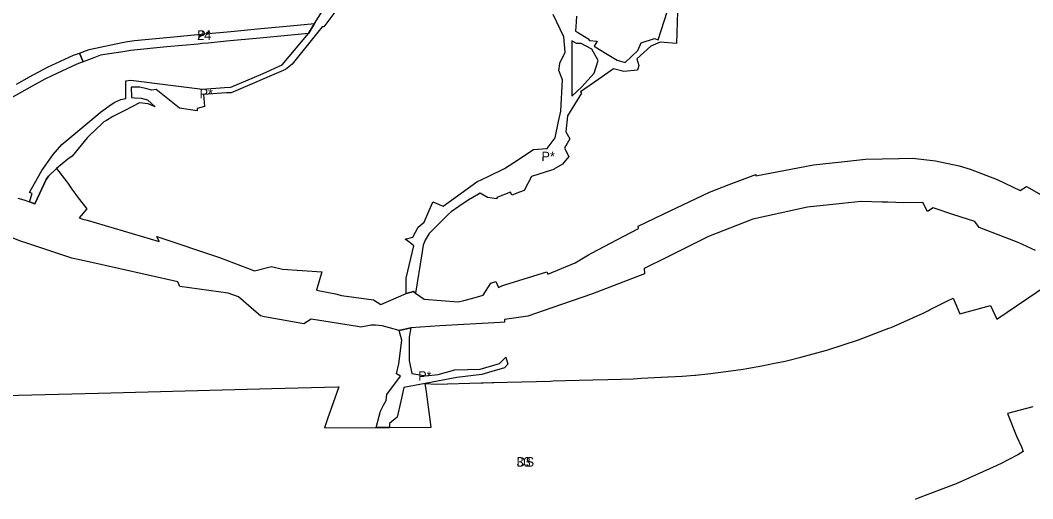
# Model space of a CAD drawing. Extents: x -501732 to -497665, y -1142022 to -1138283.
# Drawn here: x -498822 to -498074, y -1140690 to -1140337 of the extents above; entities that cross this region are included whole.
import ezdxf

# ---------------------------------------------------------------- set-up
doc = ezdxf.new("R2010")
doc.units = 0
for name, color, linetype in [('43', 7, 'Continuous'), ('44', 7, 'Continuous'), ('5', 7, 'Continuous'), ('61', 7, 'Continuous'), ('7', 7, 'Continuous')]:
    doc.layers.add(name, color=color, linetype=linetype)

msp = doc.modelspace()

# ---------------------------------------------------------------- linework, layer by layer
at = {"layer": '43'}
for points in [[(-498587.81, -1140329.06), (-498597.43, -1140341.87), (-498598.8, -1140341.98), (-498601.88, -1140345.827), (-498620.83, -1140369.5), (-498625.74, -1140373.36), (-498665.8, -1140390.54), (-498669.367, -1140390.774), (-498686.38, -1140391.89), (-498685.66, -1140400.64), (-498690.99, -1140402.25), (-498690.95, -1140403.93), (-498703.99, -1140401.95), (-498721.27, -1140388.18), (-498724.52, -1140388.76), (-498728.2, -1140387.65), (-498733.35, -1140386.55), (-498735.97, -1140386.48), (-498737.7, -1140386.43), (-498739.75, -1140386.38), (-498739.51, -1140394.23), (-498737.19, -1140394.36), (-498732.26, -1140394.64), (-498727.49, -1140395.85), (-498722.04, -1140400.93), (-498727.09, -1140398.67), (-498733.56, -1140397.95), (-498744.45, -1140403.69), (-498753.11, -1140408.26), (-498757.95, -1140411.07), (-498759.89, -1140412.2), (-498761.398, -1140413.616), (-498770.22, -1140421.9), (-498772.24, -1140423.88), (-498783.3, -1140437.31), (-498786.33, -1140439.72), (-498794.66, -1140446.57), (-498800.7, -1140452.21), (-498802.45, -1140454.72), (-498810.69, -1140472.63), (-498814.8, -1140471.18), (-498812.74, -1140465.05), (-498814.61, -1140464.19), (-498813.3, -1140461.48), (-498805.54, -1140447.97), (-498798.911, -1140438.777), (-498797.14, -1140436.32), (-498790.77, -1140428.9), (-498764.36, -1140406.72), (-498762.37, -1140405.04), (-498754.41, -1140399.29), (-498751.71, -1140397.67), (-498747.2, -1140395.62), (-498743.556, -1140394.77), (-498743.53, -1140387.04), (-498743.67, -1140383.35), (-498743.706, -1140381.726), (-498739.8, -1140381.33), (-498710.55, -1140385.04), (-498687.02, -1140387.86), (-498670.81, -1140386.81), (-498666.17, -1140386.51), (-498642.15, -1140376.28), (-498628.17, -1140370.07), (-498608.89, -1140346.84), (-498606.59, -1140343.1), (-498604.38, -1140339.37), (-498585.04, -1140308.39)], [(-498336.48, -1140330.57), (-498337.19, -1140354.3), (-498349.26, -1140353.22), (-498356.2, -1140356.09), (-498366.38, -1140365.47), (-498365.05, -1140370.57), (-498366.07, -1140373.97), (-498375.98, -1140374.82), (-498383.77, -1140372.94), (-498394.58, -1140380.5), (-498408.12, -1140389.97), (-498407.39, -1140390.94), (-498417.76, -1140407.66), (-498418.97, -1140419.34), (-498415.94, -1140424.67), (-498419.83, -1140431.49), (-498416.7, -1140437.75), (-498421.35, -1140443.39), (-498427.73, -1140447.08), (-498427.61, -1140447.29), (-498429.55, -1140447.88), (-498444.21, -1140452.41), (-498449.63, -1140462.74), (-498452.98, -1140464), (-498458.85, -1140466.21), (-498459.06, -1140465.62), (-498459.66, -1140463.92), (-498469.92, -1140467.89), (-498469.79, -1140469.06), (-498476.72, -1140467.87), (-498482.04, -1140464.87), (-498488.75, -1140468.62), (-498489.42, -1140468.99), (-498497.76, -1140474.62), (-498503.53, -1140478.64), (-498505.6, -1140480.51), (-498519.81, -1140494.63), (-498522.78, -1140499.54), (-498524.16, -1140503.18), (-498525.13, -1140509.48), (-498529.72, -1140538.53), (-498531.23, -1140537.43), (-498536.7, -1140538.87), (-498536.78, -1140527.54), (-498530.96, -1140503.56), (-498532.27, -1140502.58), (-498534, -1140501.29), (-498537.44, -1140498.71), (-498531.9, -1140497.34), (-498527.88, -1140489.95), (-498523.44, -1140486.2), (-498521.29, -1140481.1), (-498517.37, -1140471.8), (-498517.14, -1140471.25), (-498509.39, -1140474.46), (-498503.28, -1140470.04), (-498484.44, -1140456.39), (-498476.27, -1140452.44), (-498464.24, -1140446.62), (-498457.324, -1140442.101), (-498442.71, -1140432.55), (-498432.73, -1140431.71), (-498426.65, -1140423.95), (-498424.26, -1140411.9), (-498422.65, -1140404.29), (-498421.42, -1140381), (-498424.07, -1140374.16), (-498423.9, -1140372.85), (-498423.35, -1140368.66), (-498419.46, -1140360.65), (-498420.41, -1140349.26), (-498428.12, -1140332.76)], [(-498410.95, -1140334.03), (-498411.23, -1140338.15), (-498411.64, -1140345.19), (-498409.63, -1140346.38), (-498402.59, -1140350.64), (-498402.44, -1140350.81), (-498401.44, -1140351.96), (-498395.69, -1140352.4), (-498398.08, -1140356.26), (-498394, -1140358.78), (-498388.346, -1140362.103), (-498380.9, -1140366.48), (-498375.18, -1140368.36), (-498365.85, -1140359.51), (-498363.35, -1140353.74), (-498353.52, -1140350.55), (-498350.67, -1140351.45), (-498343.94, -1140330.1)], [(-498824.33, -1140384.17), (-498814.604, -1140378.848), (-498801.52, -1140371.69), (-498782.25, -1140362.86), (-498777.9, -1140361.33), (-498774.98, -1140367.75), (-498779.77, -1140369.59), (-498798.09, -1140378.22), (-498803.38, -1140380.68), (-498812.777, -1140385.826), (-498820.71, -1140390.17), (-498838.52, -1140399.91)]]:
    msp.add_lwpolyline(points, dxfattribs=at)
for points in [[(-498397.99, -1140376.21), (-498395.01, -1140366.78), (-498399.65, -1140358.41), (-498407.49, -1140354.32), (-498411.1, -1140354.18), (-498414.49, -1140352.22), (-498414.41, -1140393.14), (-498407.33, -1140386.52)], [(-498532.65, -1140598.05), (-498522.19, -1140599.71), (-498513.12, -1140598.78), (-498500.8, -1140595.31), (-498482.14, -1140594.81), (-498467.72, -1140590.56), (-498463.18, -1140585.79), (-498461.584, -1140591.01), (-498464.1, -1140593.8), (-498473.43, -1140596.49), (-498480.9, -1140598.67), (-498499.44, -1140600.8), (-498522.66, -1140605.32), (-498538.35, -1140608.28), (-498540.69, -1140618.47), (-498543.28, -1140630.12), (-498549.01, -1140634.74), (-498549.008, -1140637.715), (-498558.761, -1140637.77), (-498555.71, -1140625.83), (-498553.43, -1140621.2), (-498551.35, -1140617.79), (-498551.07, -1140613.42), (-498540.82, -1140599.94), (-498543.73, -1140598.24), (-498542.14, -1140590.72), (-498539.91, -1140573.24), (-498541.95, -1140566.19), (-498533.275, -1140564.275), (-498534.38, -1140571.05), (-498534.41, -1140583.39), (-498534.44, -1140588.39)]]:
    msp.add_lwpolyline(points, close=True, dxfattribs=at)
at = {"layer": '44'}
msp.add_lwpolyline([(-498608.89, -1140346.84), (-498644.63, -1140350.25), (-498669.42, -1140352.61), (-498682.81, -1140353.868), (-498687.19, -1140354.28), (-498690.21, -1140354.6), (-498713.32, -1140356.8), (-498740.24, -1140359.37), (-498744.18, -1140360.16), (-498762.2, -1140362.83), (-498767.22, -1140364.9), (-498774.98, -1140367.75), (-498777.9, -1140361.33), (-498770.58, -1140358.75), (-498746.33, -1140353.43), (-498742.44, -1140352.65), (-498737.12, -1140352.09), (-498710.8, -1140349.53), (-498687.95, -1140347.35), (-498685.278, -1140347.095), (-498666.05, -1140345.26), (-498643.95, -1140343.16), (-498622.2, -1140341.08), (-498604.38, -1140339.37), (-498606.59, -1140343.1)], close=True, dxfattribs=at)
at = {"layer": '5'}
for points in [[(-498911.97, -1140616.22), (-498763.779, -1140612.414), (-498635.836, -1140608.996), (-498587.232, -1140607.698), (-498586.309, -1140607.658), (-498594.68, -1140631.38), (-498596.956, -1140637.987), (-498558.761, -1140637.77), (-498549.008, -1140637.715), (-498518.24, -1140637.54), (-498521.824, -1140611.416), (-498522.66, -1140605.32), (-498514.662, -1140605.76), (-498481.482, -1140604.874), (-498479.827, -1140604.83), (-498473.333, -1140604.656), (-498471.913, -1140604.618), (-498462.065, -1140604.355), (-498440.64, -1140603.783), (-498430.138, -1140603.502), (-498428.221, -1140603.451), (-498419.006, -1140603.196), (-498398.992, -1140602.641), (-498387.928, -1140602.335), (-498377.939, -1140602.058), (-498369.099, -1140601.813), (-498363.353, -1140601.491), (-498343.694, -1140600.388), (-498343.303, -1140600.366), (-498333.112, -1140599.794), (-498323.736, -1140599.268), (-498323.104, -1140599.19), (-498314.182, -1140598.086), (-498304.366, -1140596.872), (-498287.957, -1140594.843), (-498285.35, -1140594.337), (-498274.137, -1140592.159), (-498264.802, -1140590.346), (-498257.129, -1140588.856), (-498255.131, -1140588.333), (-498245.571, -1140585.832), (-498227.312, -1140581.055), (-498225.57, -1140580.489), (-498202.84, -1140573.11), (-498196.526, -1140570.684), (-498180.452, -1140564.508), (-498178.766, -1140563.86), (-498155.285, -1140553.385), (-498151.261, -1140551.331), (-498150.408, -1140550.895), (-498137.212, -1140544.157), (-498133.079, -1140542.247), (-498132.18, -1140543.96), (-498128.1, -1140553.78), (-498105.46, -1140547.59), (-498100.702, -1140557.857), (-498049.646, -1140523.081)], [(-498074.25, -1140622.66), (-498092.81, -1140627.56), (-498086.34, -1140644.21), (-498082.67, -1140652.13), (-498081.436, -1140655.582), (-498085.369, -1140658.038), (-498098.651, -1140664.82), (-498099.854, -1140665.434), (-498101.363, -1140666.204), (-498130.852, -1140679.36), (-498140.654, -1140683.126), (-498158.761, -1140690.084), (-498161.095, -1140690.981)]]:
    msp.add_lwpolyline(points, dxfattribs=at)
at = {"layer": '7'}
for points in [[(-498823.28, -1140468.41), (-498818.81, -1140469.76), (-498814.8, -1140471.18), (-498810.69, -1140472.63), (-498802.45, -1140454.72), (-498800.7, -1140452.21), (-498794.66, -1140446.57), (-498792.98, -1140448.82), (-498786.49, -1140457.49), (-498785.41, -1140458.93), (-498783.46, -1140461.83), (-498778.67, -1140468.13), (-498772.46, -1140476.29), (-498778.07, -1140483.03), (-498775.4, -1140483.86), (-498772.22, -1140484.8), (-498719.07, -1140500.44), (-498720.83, -1140496.71), (-498674.39, -1140512.29), (-498648.73, -1140522.18), (-498635.98, -1140518.93), (-498627.99, -1140520.95), (-498598.96, -1140522.87), (-498602.81, -1140536.42), (-498588.8, -1140539.12), (-498584.45, -1140540.28), (-498560.9, -1140543.44), (-498558.02, -1140545.17), (-498555.32, -1140546.97), (-498536.7, -1140538.87), (-498531.23, -1140537.43), (-498529.72, -1140538.53), (-498523.42, -1140543.13), (-498498.25, -1140544.96), (-498494.14, -1140543.93), (-498487.43, -1140542.26), (-498479.83, -1140540.06), (-498474.26, -1140531.16), (-498470.5, -1140530.11), (-498468.47, -1140534.46), (-498466.08, -1140533.14), (-498463.8, -1140532.43), (-498432.86, -1140522.77), (-498432.24, -1140524.64), (-498411.97, -1140516.09), (-498402.08, -1140510.39), (-498399.36, -1140508.79), (-498385.8, -1140501.68), (-498365.23, -1140490.89), (-498365.57, -1140489.11), (-498347.06, -1140480.37), (-498312.78, -1140463.9), (-498298.318, -1140458.398), (-498278.66, -1140450.92), (-498278.63, -1140451.9), (-498236, -1140443.78), (-498215.5, -1140441.58), (-498197.67, -1140439.66), (-498173.045, -1140439.206), (-498162.95, -1140439.02), (-498145.98, -1140440.86), (-498128.48, -1140444.52), (-498120.5, -1140446.95), (-498100.63, -1140454.71), (-498083.46, -1140462.79), (-498078.87, -1140459.94), (-498066.42, -1140467)], [(-498072.23, -1140507.08), (-498084.94, -1140501.15), (-498113.82, -1140490.04), (-498116.99, -1140485.75), (-498133.19, -1140480.39), (-498147.91, -1140475.52), (-498151.9, -1140478.35), (-498155.29, -1140471.77), (-498169.43, -1140471.87), (-498181.21, -1140471.48), (-498185.33, -1140471.34), (-498200.94, -1140470.83), (-498215.03, -1140472.28), (-498240.65, -1140475.14), (-498280.79, -1140483.97), (-498313.48, -1140496.67), (-498344.08, -1140511.99), (-498360.97, -1140520.45), (-498360.76, -1140524.45), (-498399.15, -1140539.13), (-498429.13, -1140549.46), (-498447.03, -1140555.63), (-498464.11, -1140558.05), (-498464.12, -1140560.13), (-498467.4, -1140560.31), (-498511.96, -1140562.69), (-498533.275, -1140564.275), (-498541.95, -1140566.19), (-498548.93, -1140564.16), (-498554.35, -1140562.68), (-498559.27, -1140562.23), (-498562.5, -1140562.23), (-498570.08, -1140563.64), (-498572.57, -1140563.26), (-498606.84, -1140557.72), (-498612.14, -1140561.31), (-498641.22, -1140555.98), (-498644.25, -1140555.43), (-498647.38, -1140552.52), (-498660.45, -1140541.37), (-498668.06, -1140538.59), (-498703.71, -1140533.76), (-498705.24, -1140530.18), (-498770.79, -1140515.52), (-498783.43, -1140512.69), (-498817.31, -1140501.5), (-498820.56, -1140500.53), (-498829.89, -1140496.72)]]:
    msp.add_lwpolyline(points, dxfattribs=at)

# ---------------------------------------------------------------- texts
at = {"layer": '43'}
for rotation, p in [(359.497419, (-498689.197, -1140394.656)), (359.497417, (-498436.892, -1140441.113))]:
    msp.add_text('P*', height=7, rotation=rotation, dxfattribs=at).set_placement(p)
msp.add_text('P*', height=7, dxfattribs=at).set_placement((-498527.876, -1140603.236))
at = {"layer": '44'}
msp.add_text('P*', height=7, dxfattribs=at).set_placement((-498690.962, -1140351.544))
at = {"layer": '5'}
msp.add_text('DS', height=7, dxfattribs=at).set_placement((-498455.24, -1140666.691))
at = {"layer": '61'}
for s, p in [('24', (-498690.962, -1140351.544)), ('33', (-498455.256, -1140666.691))]:
    msp.add_text(s, height=7, dxfattribs=at).set_placement(p)

doc.saveas('drawing.dxf')
